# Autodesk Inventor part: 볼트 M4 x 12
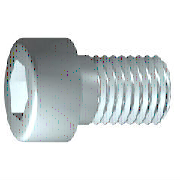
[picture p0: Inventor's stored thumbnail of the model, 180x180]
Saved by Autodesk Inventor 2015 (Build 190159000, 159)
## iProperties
IsCustomPart: 0
Created: 2012-02
Part Number: 볼트 M4 x 12
Material: 강철, 연강
Description: 6각 소켓 머리 캡 나사
Document SubType Name: Modeling
Standard: ISO 4762
Designer: mduedu
Standard Revision: Fourth edition 2004-03-01
Standards Organization: ISO
Language: ko-KR
Size Designation: M4 x 12
Categories: <MemberInstance><Categories><Category DisplayName="조임쇠" InternalName="e4da775c-781d-43d5-af7c-5136215cf5a6" Mnemonic="FSTN"><Category DisplayName="볼트" InternalN
Density: 7.75 g/cm^3
Appearance: 강철
Author: mduedu
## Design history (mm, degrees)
sketch "스케치1"
  geometry: L1 (-1, 0)-(12, 0); L2 (12, 0)-(12, 2); L3 (12, 2)-(1.75, 2); L4 (1.75, 2)-(1.32, 2); L5 (1.32, 2)-(0, 2); L6 (0, 2)-(0, 3.5); L7 (0, 3.5)-(-4, 3.5); L8 (-4, 3.5)-(-4, 1.732); L9 (-4, 1.732)-(-2, 1.732); L10 (-2, 1.732)-(-1, 0); L11 (-7.2, 0)-(15.2, 0) reference; L12 (0, -0.7)-(0, 4.2) reference; L13 (1.75, 2)-(0, 2)
  constraints: 22 end point, 6 parallel, 2 collinear, 2 perpendicular, 1 horizontal, 1 point on line
  dimensions: "d1" = 10.25 distance from line of L3.end L2 (= GEL); "d2" = 0.42952 distance of L4.end L3.end (computed from GAL); "d3" = 4 distance between parallel lines of L8 L6 (= KOH); "d4" = 2 distance of L8.end L9.end (= INTI); "d5" = 60 deg angle of L10 L1; "d6" = 4 diameter of L3 L1 (= GD); "d7" = 4 diameter of L5 L1 (= BDM); "d8" = 3.4641 diameter of L9 L1 (= 1.1547 x SW); "d9" = 7 diameter of L7 L1 (= KOD); "d26" = 12 distance between parallel lines of L12 L2 (= NLG)
revolve "본체" sketch "스케치1" stored, may be unused: angle "d10" = 90 deg
sketch "스케치2"
  geometry: L1 (0, -4.9)-(0, 4.9) reference; L2 (-4.9, 0)-(4.9, 0) reference; L3 (1.732, 0)-(0.866, -1.5); L4 (0.866, -1.5)-(-0.866, -1.5); L5 (-0.866, -1.5)-(-1.732, 0); L6 (-1.732, 0)-(-0.866, 1.5); L7 (-0.866, 1.5)-(0.866, 1.5); L8 (0.866, 1.5)-(1.732, 0); 2 further points
  constraints: 12 end point, 1 coincident, 1 horizontal alignment, 1 point on line, 12 other
extrude "슬롯" join sketch "스케치2" stored distance "d11" = 10; taper "d12" = 0 deg
workplane "Work Plane1"
fillet "Fillet2" dims "d30" = 0.1 (= R)
body "Solid1"
fillet "모깎기1" dims "d17" = 0.4 (= RR)
feature "스레드" dims "d13" = 10.25 (= GEL), "d14" = 0
chamfer "모따기1" distance "d15" = 0.42941 (= -0.5 x SPD + 0.5 x GD); stored, may be unused: second distance "d16" = 0.42941 (= GUL), angle "d27" = 45 deg
other parameters: "GD" = 4 [user parameter; used in 2 equation terms], "NLG" = 12 [user parameter; used in 1 equation term], "GEL" = 10.25 [user parameter; used in 2 equation terms], "KOD" = 7 [user parameter; used in 1 equation term], "KOH" = 4 [user parameter; used in 1 equation term], "INTI" = 2 [user parameter; used in 1 equation term], "GAL" = 0.42941 (= 0.61345 x PTC) [user parameter; used in 1 equation term], "GUL" = 0.42941 (= 0.61345 x PTC) [user parameter; used in 1 equation term], "BDM" = 4 (= NND) [user parameter; used in 1 equation term], "SW" = 3 [user parameter; used in 2 equation terms], "RR" = 0.4 [user parameter; used in 1 equation term], "SPD" = 3.14117 (= NND - 1.2269 x PTC) [user parameter; used in 1 equation term], "d19" = 0, "d28" = 0, "d29" = 0, "R" = 0.1 [user parameter; used in 1 equation term], "TOA" = 30 deg [user parameter], "GD1" = 3.14117 (= THREADDIA - 1.2269 x PTC) [user parameter], "THREADDIA" = 4 [user parameter; used in 1 equation term], "FAWI" = 45 deg [user parameter], "TPU" = 14.28571 (computed from PTC) [user parameter], "PTC" = 0.7 [user parameter; used in 5 equation terms], "NND" = 4 [user parameter; used in 2 equation terms], "E0" = 3.465 (= 1.155 x SW) [user parameter]
